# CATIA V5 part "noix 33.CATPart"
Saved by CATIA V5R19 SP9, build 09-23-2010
Part number: noix 33
Bounding box of the stored display mesh (mm): x -57.798 to -37.798, y -119.23 to -75.23, z -31.252 to 12.748
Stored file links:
  Y:\projet be 2011-12\Etude cinématique\noix 33.CATPart
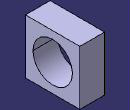
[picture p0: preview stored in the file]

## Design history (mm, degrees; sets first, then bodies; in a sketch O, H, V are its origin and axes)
Body1 (main body)
  DatumSurface1
  Sketch1 on face of DatumSurface1, origin (-57.7977, 0, 0), H (0, -1, 0), V (0, 0, 1)
    line L1 (75.2298, 12.7479) -> (119.2298, 12.7479)
    line L2 (119.2298, 12.7479) -> (119.2298, -31.2521)
    line L3 (119.2298, -31.2521) -> (75.2298, -31.2521)
    line L4 (75.2298, -31.2521) -> (75.2298, 12.7479)
    circle A1 centre (97.2298, -9.2521) radius 16
    point P5 (97.2298, -9.2521)
    length L1 = 44
    length L2 = 44
    radius A1 = 16
    distance P5 L4 = 22
    distance P5 L3 = 22
    horizontal: L1 H, L3 H
    vertical: L2 V, L4 V
  Pad1: profile Sketch1, direction (1, 0, 0), length 20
